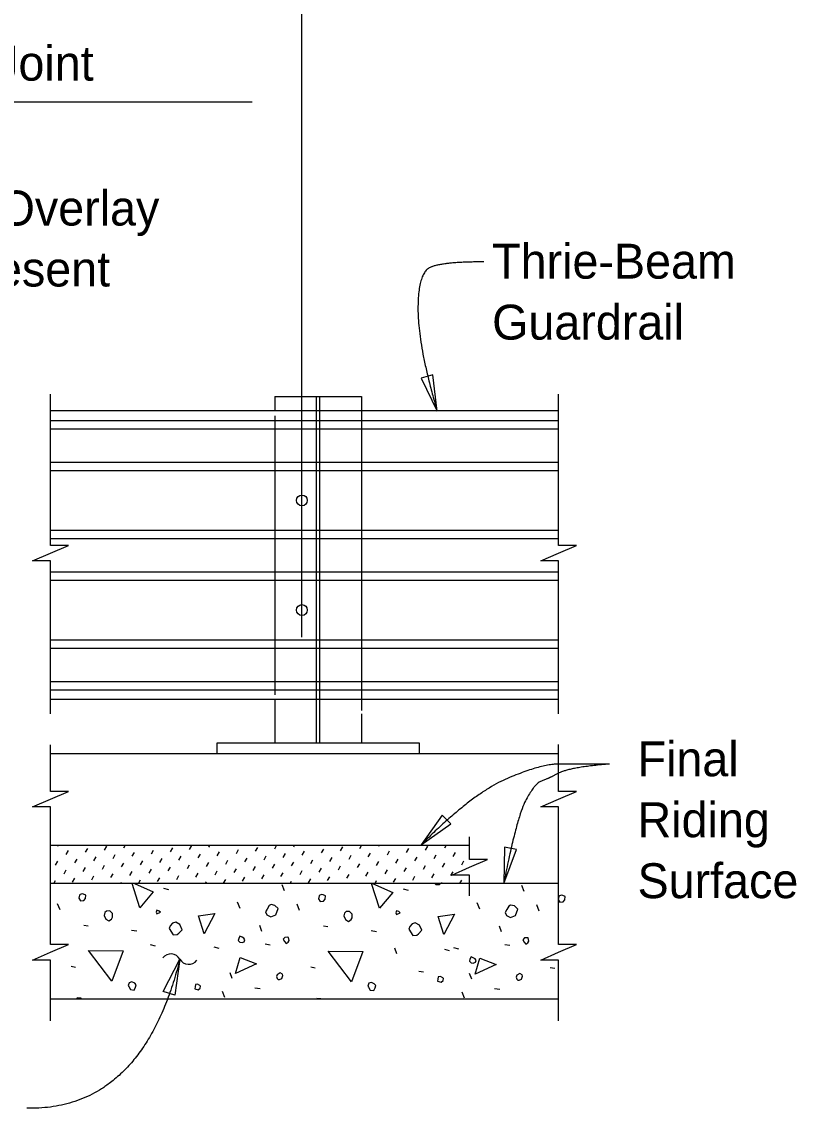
# Model space of a CAD drawing. Extents: x 21516.9 to 21586.2, y 56155.7 to 56195.
# Drawn here: x 21532.55 to 21537.02, y 56169.96 to 56176.24 of the extents above; entities that cross this region are included whole.
import ezdxf

# ---------------------------------------------------------------- set-up
doc = ezdxf.new("R2010")
doc.units = 0
for name, color, linetype in [('AdhocPoint_dp', 7, 'Continuous'), ('Border', 7, 'Continuous'), ('Patterning', 7, 'Continuous'), ('PlotBorder_dp', 7, 'Continuous'), ('SheetBorder_dp', 7, 'Continuous'), ('TextMisc', 7, 'Continuous')]:
    doc.layers.add(name, color=color, linetype=linetype)

msp = doc.modelspace()

# ---------------------------------------------------------------- linework, layer by layer
at = {"layer": 'AdhocPoint_dp'}
for p, q in [((21532.7121, 56172.0121), (21535.6477, 56172.0121)), ((21535.1335, 56171.4811), (21532.7121, 56171.4811)), ((21535.6477, 56171.2621), (21532.7121, 56171.2621)), ((21532.7121, 56170.5954), (21535.6477, 56170.5954))]:
    msp.add_line(p, q, dxfattribs=at)
at = {"layer": 'Border'}
for p, q in [((21532.7546, 56171.4783), (21532.7562, 56171.4811)), ((21533.0247, 56171.4554), (21533.0377, 56171.4778)), ((21533.1354, 56171.4684), (21533.1427, 56171.4811)), ((21533.4055, 56171.4455), (21533.4184, 56171.4678)), ((21533.5161, 56171.4584), (21533.5291, 56171.4808)), ((21533.6267, 56171.4714), (21533.6323, 56171.4811)), ((21533.8968, 56171.4485), (21533.9098, 56171.4709)), ((21534.0075, 56171.4614), (21534.0188, 56171.4811)), ((21534.1181, 56171.4744), (21534.122, 56171.4811)), ((21534.3882, 56171.4515), (21534.4012, 56171.4739)), ((21534.4988, 56171.4645), (21534.5084, 56171.4811)), ((21534.6095, 56171.4774), (21534.6116, 56171.4811)), ((21534.8796, 56171.4545), (21534.8925, 56171.4769)), ((21534.9902, 56171.4675), (21534.9981, 56171.4811)), ((21535.1008, 56171.4804), (21535.1012, 56171.4811)), ((21532.8035, 56171.4295), (21532.8164, 56171.4519)), ((21532.8523, 56171.3806), (21532.8653, 56171.403)), ((21532.9141, 56171.4424), (21532.9271, 56171.4648)), ((21532.9629, 56171.3936), (21532.9759, 56171.416)), ((21533.0736, 56171.4066), (21533.0865, 56171.429)), ((21533.1842, 56171.4195), (21533.1972, 56171.4419)), ((21533.2948, 56171.4325), (21533.3078, 56171.4549)), ((21533.3437, 56171.3837), (21533.3566, 56171.406)), ((21533.4543, 56171.3966), (21533.4673, 56171.419)), ((21533.5649, 56171.4096), (21533.5779, 56171.432)), ((21533.6756, 56171.4225), (21533.6885, 56171.4449)), ((21533.7862, 56171.4355), (21533.7992, 56171.4579)), ((21533.835, 56171.3867), (21533.848, 56171.4091)), ((21533.9457, 56171.3996), (21533.9586, 56171.422)), ((21534.0563, 56171.4126), (21534.0693, 56171.435)), ((21534.1669, 56171.4256), (21534.1799, 56171.448)), ((21534.2776, 56171.4385), (21534.2905, 56171.4609)), ((21534.3264, 56171.3897), (21534.3394, 56171.4121)), ((21534.437, 56171.4027), (21534.45, 56171.425)), ((21534.5477, 56171.4156), (21534.5606, 56171.438)), ((21534.6583, 56171.4286), (21534.6713, 56171.451)), ((21534.7689, 56171.4415), (21534.7819, 56171.4639)), ((21534.8178, 56171.3927), (21534.8307, 56171.4151)), ((21534.9284, 56171.4057), (21534.9414, 56171.4281)), ((21535.039, 56171.4186), (21535.052, 56171.441)), ((21532.7417, 56171.3677), (21532.7546, 56171.3901)), ((21532.7905, 56171.3188), (21532.8035, 56171.3412)), ((21532.9011, 56171.3318), (21532.9141, 56171.3542)), ((21533.0118, 56171.3448), (21533.0247, 56171.3672)), ((21533.1224, 56171.3577), (21533.1354, 56171.3801)), ((21533.233, 56171.3707), (21533.246, 56171.3931)), ((21533.2819, 56171.3219), (21533.2948, 56171.3442)), ((21533.3925, 56171.3348), (21533.4055, 56171.3572)), ((21533.5031, 56171.3478), (21533.5161, 56171.3702)), ((21533.6138, 56171.3607), (21533.6267, 56171.3831)), ((21533.7244, 56171.3737), (21533.7374, 56171.3961)), ((21533.7732, 56171.3249), (21533.7862, 56171.3473)), ((21533.8839, 56171.3378), (21533.8968, 56171.3602)), ((21533.9945, 56171.3508), (21534.0075, 56171.3732)), ((21534.1051, 56171.3638), (21534.1181, 56171.3862)), ((21534.2158, 56171.3767), (21534.2287, 56171.3991)), ((21534.2646, 56171.3279), (21534.2776, 56171.3503)), ((21534.3752, 56171.3409), (21534.3882, 56171.3633)), ((21534.4859, 56171.3538), (21534.4988, 56171.3762)), ((21534.5965, 56171.3668), (21534.6095, 56171.3892)), ((21534.6453, 56171.318), (21534.6583, 56171.3403)), ((21534.7071, 56171.3798), (21534.7201, 56171.4021)), ((21534.756, 56171.3309), (21534.7689, 56171.3533)), ((21534.8666, 56171.3439), (21534.8796, 56171.3663)), ((21534.9772, 56171.3568), (21534.9902, 56171.3792)), ((21535.0879, 56171.3698), (21535.1008, 56171.3922)), ((21532.7316, 56171.2621), (21532.7417, 56171.2794)), ((21532.8393, 56171.27), (21532.8523, 56171.2924)), ((21532.95, 56171.283), (21532.9629, 56171.3054)), ((21533.0606, 56171.2959), (21533.0736, 56171.3183)), ((21533.1712, 56171.3089), (21533.1842, 56171.3313)), ((21533.2213, 56171.2622), (21533.233, 56171.2824)), ((21533.3307, 56171.273), (21533.3437, 56171.2954)), ((21533.4413, 56171.286), (21533.4543, 56171.3084)), ((21533.552, 56171.2989), (21533.5649, 56171.3213)), ((21533.6626, 56171.3119), (21533.6756, 56171.3343)), ((21533.7114, 56171.2631), (21533.7244, 56171.2855)), ((21533.8221, 56171.276), (21533.835, 56171.2984)), ((21533.9327, 56171.289), (21533.9457, 56171.3114)), ((21534.0433, 56171.302), (21534.0563, 56171.3244)), ((21534.154, 56171.3149), (21534.1669, 56171.3373)), ((21534.2028, 56171.2661), (21534.2158, 56171.2885)), ((21534.3134, 56171.2791), (21534.3264, 56171.3015)), ((21534.4241, 56171.292), (21534.437, 56171.3144)), ((21534.5347, 56171.305), (21534.5477, 56171.3274)), ((21534.5871, 56171.2623), (21534.5965, 56171.2785)), ((21534.6942, 56171.2691), (21534.7071, 56171.2915)), ((21534.8048, 56171.2821), (21534.8178, 56171.3045)), ((21534.9154, 56171.295), (21534.9284, 56171.3174)), ((21535.0261, 56171.308), (21535.039, 56171.3304)), ((21535.0768, 56171.2624), (21535.0879, 56171.2816)), ((21533.1181, 56171.2621), (21533.1224, 56171.2695)), ((21533.3657, 56171.2349), (21533.394, 56171.2279)), ((21533.6078, 56171.2622), (21533.6138, 56171.2725)), ((21533.9943, 56171.2623), (21533.9945, 56171.2626)), ((21534.064, 56171.219), (21534.0498, 56171.2544)), ((21534.0975, 56171.2623), (21534.1051, 56171.2755)), ((21534.484, 56171.2623), (21534.4859, 56171.2656)), ((21534.7504, 56171.2314), (21534.7787, 56171.2243)), ((21534.9736, 56171.2624), (21534.9772, 56171.2686)), ((21535.4487, 56171.2155), (21535.4345, 56171.2508)), ((21533.8076, 56171.1183), (21533.7935, 56171.1536)), ((21532.7671, 56171.1101), (21532.7529, 56171.1454)), ((21534.1517, 56171.1065), (21534.1376, 56171.1419)), ((21535.1923, 56171.1147), (21535.1782, 56171.1501)), ((21535.5364, 56171.103), (21535.5223, 56171.1383)), ((21532.9049, 56171.0217), (21532.9297, 56171.0181)), ((21533.1807, 56170.9934), (21533.2108, 56170.9881)), ((21533.9332, 56170.9857), (21533.9208, 56171.0193)), ((21534.2896, 56171.0181), (21534.3144, 56171.0146)), ((21534.5654, 56170.9898), (21534.5954, 56170.9845)), ((21535.3178, 56170.9821), (21535.3055, 56171.0157)), ((21533.2876, 56170.9095), (21533.3159, 56170.9024)), ((21533.952, 56170.9138), (21533.982, 56170.9085)), ((21535.3367, 56170.9103), (21535.3667, 56170.905)), ((21533.6556, 56170.8955), (21533.6839, 56170.8885)), ((21534.7139, 56170.8555), (21534.7015, 56170.8891)), ((21534.9879, 56170.882), (21535.0162, 56170.8749)), ((21535.0403, 56170.892), (21535.0686, 56170.8849)), ((21532.8307, 56170.7848), (21532.8572, 56170.7795)), ((21534.2154, 56170.7812), (21534.2419, 56170.7759)), ((21535.6001, 56170.7777), (21535.6266, 56170.7724)), ((21533.7617, 56170.7129), (21533.7493, 56170.7465)), ((21534.8412, 56170.7565), (21534.8677, 56170.7512)), ((21535.1464, 56170.7094), (21535.134, 56170.743)), ((21533.8919, 56170.6593), (21533.9237, 56170.6557)), ((21535.2766, 56170.6557), (21535.3084, 56170.6522)), ((21533.7193, 56170.6033), (21533.7051, 56170.6387)), ((21535.1039, 56170.5998), (21535.0898, 56170.6351))]:
    msp.add_line(p, q, dxfattribs=at)
for points in [[(21533.2284, 56171.1224), (21533.183, 56171.2621)], [(21533.1969, 56171.2621), (21533.3062, 56171.2144), (21533.2284, 56171.1224)], [(21534.6131, 56171.1189), (21534.5665, 56171.2621)], [(21534.5735, 56171.2621), (21534.6909, 56171.2108), (21534.6131, 56171.1189)], [(21534.9352, 56171.2621), (21534.9378, 56171.2562), (21534.9342, 56171.2597)], [(21534.9378, 56171.2562), (21534.959, 56171.2562), (21534.9649, 56171.2621)], [(21532.8767, 56171.1772), (21532.8855, 56171.1613), (21532.9049, 56171.1631), (21532.9138, 56171.1755), (21532.9156, 56171.1949), (21532.9032, 56171.2002), (21532.8943, 56171.202), (21532.8837, 56171.1984), (21532.8802, 56171.1949), (21532.8767, 56171.1772)], [(21534.2613, 56171.1737), (21534.2702, 56171.1578), (21534.2896, 56171.1595), (21534.2985, 56171.1719), (21534.3002, 56171.1914), (21534.2879, 56171.1967), (21534.279, 56171.1984), (21534.2684, 56171.1949), (21534.2649, 56171.1914), (21534.2613, 56171.1737)], [(21535.646, 56171.1702), (21535.6549, 56171.1542), (21535.6743, 56171.156), (21535.6831, 56171.1684), (21535.6849, 56171.1878), (21535.6725, 56171.1931), (21535.6637, 56171.1949), (21535.6531, 56171.1914), (21535.6496, 56171.1878), (21535.646, 56171.1702)], [(21533.0216, 56171.0782), (21533.0322, 56171.057), (21533.0499, 56171.0464), (21533.064, 56171.057), (21533.0711, 56171.0676), (21533.0711, 56171.0888), (21533.0552, 56171.1047), (21533.0358, 56171.103), (21533.0269, 56171.0941), (21533.0216, 56171.0782)], [(21533.3274, 56171.0871), (21533.3469, 56171.0959), (21533.3398, 56171.103), (21533.3274, 56171.1083), (21533.3221, 56171.0959), (21533.3274, 56171.0871)], [(21533.9614, 56171.0811), (21533.9844, 56171.0688), (21534.0145, 56171.0811), (21534.0269, 56171.1183), (21534.0092, 56171.1359), (21533.9862, 56171.1412), (21533.9756, 56171.1342), (21533.9632, 56171.1147), (21533.9544, 56171.0988), (21533.9614, 56171.0811)], [(21534.4063, 56171.0747), (21534.4169, 56171.0535), (21534.4346, 56171.0429), (21534.4487, 56171.0535), (21534.4558, 56171.0641), (21534.4558, 56171.0853), (21534.4399, 56171.1012), (21534.4204, 56171.0994), (21534.4116, 56171.0906), (21534.4063, 56171.0747)], [(21534.7121, 56171.0835), (21534.7316, 56171.0924), (21534.7245, 56171.0994), (21534.7121, 56171.1047), (21534.7068, 56171.0924), (21534.7121, 56171.0835)], [(21535.3461, 56171.0776), (21535.3691, 56171.0652), (21535.3992, 56171.0776), (21535.4115, 56171.1147), (21535.3939, 56171.1324), (21535.3709, 56171.1377), (21535.3603, 56171.1306), (21535.3479, 56171.1112), (21535.3391, 56171.0953), (21535.3461, 56171.0776)], [(21533.3982, 56171.0022), (21533.4211, 56170.9651), (21533.4441, 56170.9669), (21533.453, 56170.9757), (21533.4724, 56170.9951), (21533.46, 56171.0252), (21533.4353, 56171.0393), (21533.4176, 56171.0323), (21533.4035, 56171.0181), (21533.3982, 56171.0022)], [(21533.6008, 56170.9715), (21533.5672, 56171.0758), (21533.6609, 56171.0882), (21533.6008, 56170.9715)], [(21534.7828, 56170.9987), (21534.8058, 56170.9616), (21534.8288, 56170.9633), (21534.8376, 56170.9722), (21534.8571, 56170.9916), (21534.8447, 56171.0217), (21534.82, 56171.0358), (21534.8023, 56171.0287), (21534.7881, 56171.0146), (21534.7828, 56170.9987)], [(21534.9855, 56170.968), (21534.9519, 56171.0723), (21535.0456, 56171.0847), (21534.9855, 56170.968)], [(21533.8066, 56170.9226), (21533.8189, 56170.9208), (21533.8313, 56170.9261), (21533.8348, 56170.9367), (21533.8295, 56170.9455), (21533.8189, 56170.9526), (21533.8066, 56170.9579), (21533.7995, 56170.9438), (21533.7959, 56170.9332), (21533.8066, 56170.9226)], [(21534.0633, 56170.9262), (21534.074, 56170.9156), (21534.0846, 56170.9227), (21534.0916, 56170.9333), (21534.0881, 56170.951), (21534.0793, 56170.9527), (21534.0669, 56170.951), (21534.0563, 56170.9403), (21534.0633, 56170.9262)], [(21535.448, 56170.9227), (21535.4586, 56170.9121), (21535.4692, 56170.9191), (21535.4763, 56170.9297), (21535.4728, 56170.9474), (21535.4639, 56170.9492), (21535.4516, 56170.9474), (21535.441, 56170.9368), (21535.448, 56170.9227)], [(21533.0658, 56170.6982), (21532.9315, 56170.8749), (21533.1312, 56170.8732), (21533.0658, 56170.6982)], [(21534.4505, 56170.6946), (21534.3161, 56170.8714), (21534.5159, 56170.8696), (21534.4505, 56170.6946)], [(21535.1428, 56170.8036), (21535.1552, 56170.8018), (21535.1676, 56170.8071), (21535.1711, 56170.8177), (21535.1658, 56170.8266), (21535.1552, 56170.8337), (21535.1428, 56170.839), (21535.1358, 56170.8248), (21535.1322, 56170.8142), (21535.1428, 56170.8036)], [(21533.7805, 56170.7424), (21533.8088, 56170.8343), (21533.9025, 56170.7972), (21533.7805, 56170.7424)], [(21535.1652, 56170.7388), (21535.1935, 56170.8307), (21535.2872, 56170.7936), (21535.1652, 56170.7388)], [(21534.028, 56170.707), (21534.0351, 56170.707), (21534.0492, 56170.7141), (21534.0545, 56170.73), (21534.0527, 56170.7388), (21534.0386, 56170.7459), (21534.0209, 56170.7353), (21534.0174, 56170.7247), (21534.0209, 56170.7141), (21534.028, 56170.707)], [(21534.949, 56170.6982), (21534.9684, 56170.6929), (21534.9808, 56170.7017), (21534.9826, 56170.7141), (21534.9791, 56170.7176), (21534.9649, 56170.7247), (21534.9525, 56170.7229), (21534.9508, 56170.7105), (21534.949, 56170.6982)], [(21535.4127, 56170.7035), (21535.4197, 56170.7035), (21535.4339, 56170.7105), (21535.4392, 56170.7264), (21535.4374, 56170.7353), (21535.4233, 56170.7424), (21535.4056, 56170.7317), (21535.4021, 56170.7211), (21535.4056, 56170.7105), (21535.4127, 56170.7035)], [(21533.1648, 56170.6663), (21533.1736, 56170.6504), (21533.1949, 56170.6469), (21533.2037, 56170.6628), (21533.2072, 56170.6769), (21533.1984, 56170.6858), (21533.1825, 56170.6946), (21533.1666, 56170.6893), (21533.1613, 56170.6734), (21533.1648, 56170.6663)], [(21533.5457, 56170.6534), (21533.5651, 56170.6481), (21533.5775, 56170.6569), (21533.5793, 56170.6693), (21533.5757, 56170.6728), (21533.5616, 56170.6799), (21533.5492, 56170.6781), (21533.5474, 56170.6657), (21533.5457, 56170.6534)], [(21534.5495, 56170.6628), (21534.5583, 56170.6469), (21534.5795, 56170.6434), (21534.5884, 56170.6593), (21534.5919, 56170.6734), (21534.5831, 56170.6823), (21534.5672, 56170.6911), (21534.5513, 56170.6858), (21534.5459, 56170.6699), (21534.5495, 56170.6628)], [(21532.8901, 56170.5954), (21532.889, 56170.5992), (21532.8661, 56170.6009), (21532.8642, 56170.5954)], [(21534.2738, 56170.5954), (21534.2737, 56170.5956), (21534.2507, 56170.5974), (21534.2501, 56170.5954)]]:
    msp.add_lwpolyline(points, dxfattribs=at)
at = {"layer": 'Patterning'}
for p, q in [((21534.2481, 56172.0747), (21534.2481, 56174.0747)), ((21534.2689, 56172.0747), (21534.2689, 56174.0747)), ((21534.5085, 56174.0747), (21534.5085, 56172.2617)), ((21534.0085, 56173.9628), (21534.0085, 56172.3509))]:
    msp.add_line(p, q, dxfattribs=at)
at = {"layer": 'PlotBorder_dp'}
for p, q in [((21534.1647, 56172.6838), (21534.1647, 56186.7281)), ((21533.8765, 56175.7746), (21528.3251, 56175.7746))]:
    msp.add_line(p, q, dxfattribs=at)
for points in [[(21534.9465, 56173.9905), (21534.9215, 56174.2002), (21534.8538, 56174.1802)], [(21534.8531, 56171.4852), (21535.0253, 56171.6075), (21534.9754, 56171.6574)], [(21535.3305, 56171.2616), (21535.4052, 56171.4592), (21535.3359, 56171.4728)], [(21533.46, 56170.8253), (21533.4295, 56170.6163), (21533.3624, 56170.638)]]:
    msp.add_lwpolyline(points, close=True, dxfattribs=at)
for points in [[(21532.7121, 56172.2416), (21532.7121, 56173.1248), (21532.6088, 56173.1248), (21532.7121, 56173.1698), (21532.8155, 56173.2148), (21532.7121, 56173.2148), (21532.7121, 56174.0878)], [(21535.6477, 56172.2416), (21535.6477, 56173.1248), (21535.5444, 56173.1248), (21535.6477, 56173.1698), (21535.751, 56173.2148), (21535.6477, 56173.2148), (21535.6477, 56174.0878)], [(21532.7121, 56171.2342), (21532.7121, 56171.7042), (21532.6088, 56171.7042), (21532.7121, 56171.7492), (21532.8155, 56171.7942), (21532.7121, 56171.7942), (21532.7121, 56172.0622)], [(21535.6477, 56171.2342), (21535.6477, 56171.7042), (21535.5444, 56171.7042), (21535.6477, 56171.7492), (21535.751, 56171.7942), (21535.6477, 56171.7942), (21535.6477, 56172.0651)], [(21535.1335, 56171.1902), (21535.1335, 56171.311), (21535.0302, 56171.311), (21535.1335, 56171.356), (21535.2368, 56171.401), (21535.1335, 56171.401), (21535.1335, 56171.5316)], [(21532.7121, 56170.4691), (21532.7121, 56170.8197), (21532.6088, 56170.8197), (21532.7121, 56170.8647), (21532.8155, 56170.9097), (21532.7121, 56170.9097), (21532.7121, 56171.2342)], [(21535.6477, 56170.4691), (21535.6477, 56170.8197), (21535.5444, 56170.8197), (21535.6477, 56170.8647), (21535.751, 56170.9097), (21535.6477, 56170.9097), (21535.6477, 56171.2342)]]:
    msp.add_lwpolyline(points, dxfattribs=at)
for centre, start, end in [((21533.4076, 56170.7957), 30.00813, 141.73535), ((21533.5109, 56170.8553), 210.00813, 321.73535)]:
    msp.add_arc(centre, 0.0596, start, end, dxfattribs=at)
for points in [[(21535.2168, 56174.8521), (21534.9766, 56174.8521), (21534.8352, 56174.7884), (21534.8352, 56174.3678), (21534.9465, 56173.9904)], [(21535.9415, 56171.9518), (21535.7507, 56171.9518), (21535.5457, 56171.9518), (21535.15, 56171.7821), (21534.8531, 56171.4852)], [(21535.9415, 56171.9518), (21535.7157, 56171.9333), (21535.592, 56171.8697), (21535.5089, 56171.8397), (21535.4047, 56171.6399), (21535.3305, 56171.2616)], [(21533.46, 56170.8253), (21533.2394, 56169.9516), (21532.576, 56169.9639)]]:
    msp.add_open_spline(points, degree=2, dxfattribs=at)
at = {"layer": 'TextMisc'}
for p, q in [((21534.0085, 56174.0747), (21534.5085, 56174.0747)), ((21534.0085, 56174.0747), (21534.0085, 56173.9913)), ((21535.6477, 56173.9913), (21532.7121, 56173.9913)), ((21532.7121, 56173.9357), (21535.6477, 56173.9357)), ((21532.7121, 56173.8875), (21535.6477, 56173.8875)), ((21532.7121, 56173.6947), (21535.6477, 56173.6947)), ((21532.7121, 56173.6465), (21535.6477, 56173.6465)), ((21532.7121, 56173.3025), (21535.6477, 56173.3025)), ((21532.7121, 56173.2543), (21535.6477, 56173.2543)), ((21532.7121, 56173.0615), (21535.6477, 56173.0615)), ((21532.7121, 56173.0133), (21535.6477, 56173.0133)), ((21532.7121, 56172.6694), (21535.6477, 56172.6694)), ((21532.7121, 56172.6212), (21535.6477, 56172.6212)), ((21532.7121, 56172.4283), (21535.6477, 56172.4283)), ((21532.7121, 56172.3801), (21535.6477, 56172.3801)), ((21535.6477, 56172.3246), (21532.7121, 56172.3246)), ((21534.0085, 56172.3247), (21534.0085, 56172.0747)), ((21534.5085, 56172.2413), (21534.5085, 56172.0747)), ((21533.6751, 56172.0747), (21534.8418, 56172.0747)), ((21533.6751, 56172.0122), (21533.6751, 56172.0747)), ((21534.0085, 56172.0747), (21534.5085, 56172.0747)), ((21534.8418, 56172.0747), (21534.8418, 56172.0122)), ((21533.6751, 56172.0122), (21534.8418, 56172.0122))]:
    msp.add_line(p, q, dxfattribs=at)
for centre in [(21534.1647, 56173.4746), (21534.1647, 56172.8414)]:
    msp.add_circle(centre, 0.0312, dxfattribs=at)

# ---------------------------------------------------------------- texts
at = {"layer": 'PlotBorder_dp'}
for s, p in [('Asphalt Overlay', (21531.4381, 56175.0621)), ('when present', (21531.4381, 56174.7101)), ('Thrie-Beam ', (21535.2637, 56174.7554)), ('Guardrail', (21535.2637, 56174.4034)), ('Final ', (21536.1041, 56171.8814)), ('Riding ', (21536.1041, 56171.5294)), ('Surface', (21536.1041, 56171.1774))]:
    msp.add_text(s, height=0.2016, dxfattribs=at).set_placement(p)
at = {"layer": 'SheetBorder_dp'}
msp.add_text('Intermediate Deck Joint', height=0.2016, dxfattribs=at).set_placement((21530.1294, 56175.8989))

doc.saveas('drawing.dxf')
